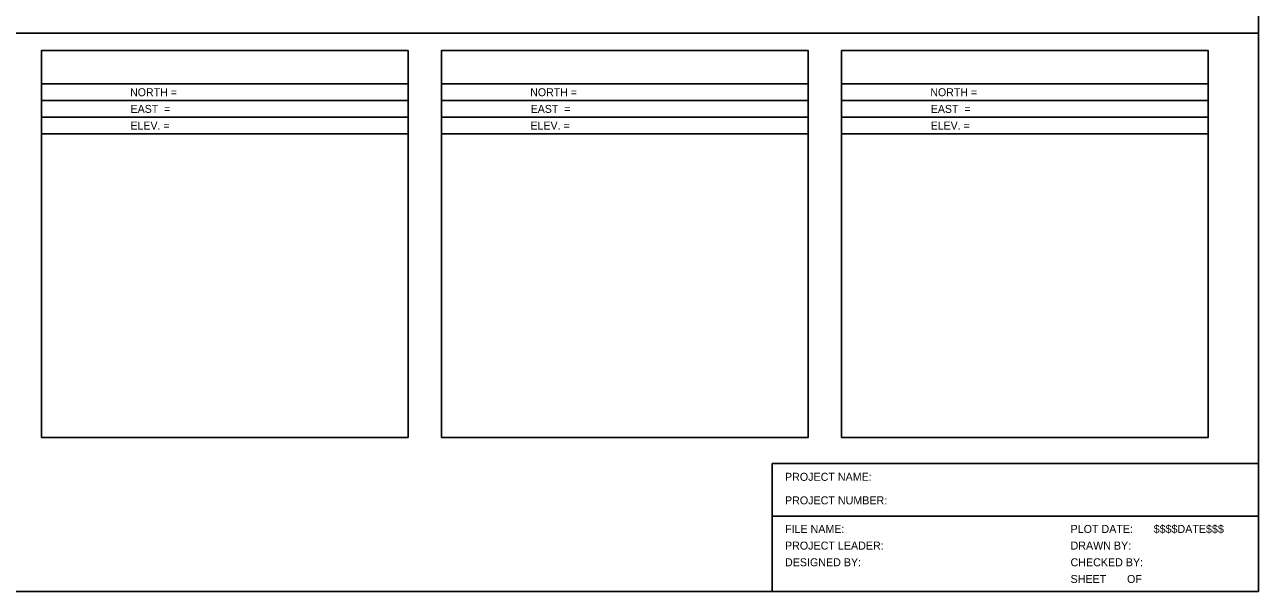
# Model space of a CAD drawing. Extents: x 1620714 to 1621354, y 115592 to 116012.
# Drawn here: x 1620984.2 to 1621354.2, y 115592 to 115761.9 of the extents above; entities that cross this region are included whole.
import ezdxf

# ---------------------------------------------------------------- set-up
doc = ezdxf.new("R2010")
doc.units = 0
doc.layers.add('NBL1', color=7, linetype='Continuous')

msp = doc.modelspace()

# ---------------------------------------------------------------- linework, layer by layer
at = {"layer": 'NBL1'}
for p, q in [((1620714.21, 115759.34), (1621354.21, 115759.34)), ((1621099.21, 115744.17), (1620989.21, 115744.17)), ((1621219.21, 115744.17), (1621109.21, 115744.17)), ((1621339.21, 115744.17), (1621229.21, 115744.17)), ((1621099.21, 115739.17), (1620989.21, 115739.17)), ((1621219.21, 115739.17), (1621109.21, 115739.17)), ((1621339.21, 115739.17), (1621229.21, 115739.17)), ((1621099.21, 115734.17), (1620989.21, 115734.17)), ((1621219.21, 115734.17), (1621109.21, 115734.17)), ((1621339.21, 115734.17), (1621229.21, 115734.17)), ((1621099.21, 115729.17), (1620989.21, 115729.17)), ((1621219.21, 115729.17), (1621109.21, 115729.17)), ((1621339.21, 115729.17), (1621229.21, 115729.17)), ((1621208.37, 115630.34), (1621354.21, 115630.34)), ((1621208.37, 115592), (1621208.37, 115630.34)), ((1621208.37, 115614.5), (1621354.21, 115614.5))]:
    msp.add_line(p, q, dxfattribs=at)
for points in [[(1621354.21, 115592), (1620714.21, 115592), (1620714.21, 116012), (1621354.21, 116012)], [(1620989.21, 115638.17), (1621099.21, 115638.17), (1621099.21, 115754.17), (1620989.21, 115754.17)], [(1621109.21, 115638.17), (1621219.21, 115638.17), (1621219.21, 115754.17), (1621109.21, 115754.17)], [(1621229.21, 115638.17), (1621339.21, 115638.17), (1621339.21, 115754.17), (1621229.21, 115754.17)]]:
    msp.add_lwpolyline(points, close=True, dxfattribs=at)

# ---------------------------------------------------------------- texts
for s, height, p in [('NORTH =             ', 2.375, (1621015.83, 115740.48)), ('NORTH =             ', 2.375, (1621135.83, 115740.48)), ('NORTH =             ', 2.375, (1621255.83, 115740.48)), ('EAST  =             ', 2.375, (1621015.97, 115735.48)), ('EAST  =             ', 2.375, (1621135.97, 115735.48)), ('EAST  =             ', 2.375, (1621255.97, 115735.48)), ('ELEV. =             ', 2.375, (1621015.93, 115730.48)), ('ELEV. =             ', 2.375, (1621135.93, 115730.48)), ('ELEV. =             ', 2.375, (1621255.93, 115730.48)), ('PROJECT NAME:', 2.4, (1621212.24, 115625.14)), ('PROJECT NUMBER:', 2.4, (1621212.24, 115618.08)), ('FILE NAME:', 2.4, (1621212.24, 115609.51)), ('PLOT DATE:', 2.4, (1621297.89, 115609.51)), ('$$$$DATE$$$', 2.4, (1621322.82, 115609.51)), ('PROJECT LEADER:', 2.4, (1621212.24, 115604.51)), ('DRAWN BY:', 2.4, (1621297.89, 115604.51)), ('DESIGNED BY:', 2.4, (1621212.24, 115599.51)), ('CHECKED BY:', 2.4, (1621297.89, 115599.51)), ('SHEET       OF', 2.4, (1621297.89, 115594.51))]:
    msp.add_text(s, height=height, dxfattribs=at).set_placement(p)

doc.saveas('drawing.dxf')
